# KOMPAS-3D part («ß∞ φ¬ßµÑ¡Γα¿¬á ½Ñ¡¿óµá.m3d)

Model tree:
1. Эскиз:1
2. Операция выдавливания:1
     Расстояние 1 = 149.4; Расстояние 2 = 64
3. Скругление:1
     Радиус = 0.2

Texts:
  ось эксцентрика ленивца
